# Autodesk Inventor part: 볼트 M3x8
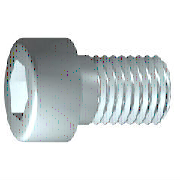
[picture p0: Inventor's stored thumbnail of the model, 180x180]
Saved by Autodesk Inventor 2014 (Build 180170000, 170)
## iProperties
IsCustomPart: 0
Created: 2012-02
Part Number: 볼트 M3x8
Material: 강철, 연강
Description: 6각머리 태핑 나사
Document SubType Name: Modeling
Standard: KS B 1003
Designer: mduedu
Standards Organization: KS
Language: ko-KR
Size Designation: M 3 x 8
Categories: <MemberInstance><Categories><Category DisplayName="조임쇠" InternalName="e4da775c-781d-43d5-af7c-5136215cf5a6" Mnemonic="FSTN"><Category DisplayName="볼트" InternalN
Density: 1 g/cm^3
Appearance: 강철
Author: mduedu
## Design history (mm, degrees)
sketch "스케치1"
  geometry: L1 (-0.867, 0)-(8, 0); L2 (8, 0)-(8, 1.5); L3 (8, 1.5)-(1.25, 1.5); L4 (1.25, 1.5)-(0.943, 1.5); L5 (0.943, 1.5)-(0, 1.5); L6 (0, 1.5)-(0, 2.75); L7 (0, 2.75)-(-3, 2.75); L8 (-3, 2.75)-(-3, 1.443); L9 (-3, 1.443)-(-1.7, 1.443); L10 (-1.7, 1.443)-(-0.867, 0); L11 (-5.2, 0)-(10.2, 0) reference; L12 (0, -0.55)-(0, 3.3) reference; L13 (1.25, 1.5)-(0, 1.5)
  constraints: 22 end point, 6 parallel, 2 collinear, 2 perpendicular, 1 horizontal, 1 point on line
  dimensions: "d1" = 6.75 distance from line of L3.end L2 (= GEL); "d2" = 0.30683 distance of L4.end L3.end (computed from GAL); "d3" = 3 distance between parallel lines of L8 L6 (= KOH); "d4" = 1.3 distance of L8.end L9.end (= INTI); "d5" = 60 deg angle of L10 L1; "d6" = 3 diameter of L3 L1 (= GD); "d7" = 3 diameter of L5 L1 (= BDM); "d8" = 2.88675 diameter of L9 L1 (= 1.1547 x SW); "d9" = 5.5 diameter of L7 L1 (= KOD); "d26" = 8 distance between parallel lines of L12 L2 (= NLG)
revolve "본체" sketch "스케치1" stored, may be unused: angle "d10" = 90 deg
sketch "스케치2"
  geometry: L1 (0, -3.85)-(0, 3.85) reference; L2 (-3.85, 0)-(3.85, 0) reference; L3 (1.443, 0)-(0.722, -1.25); L4 (0.722, -1.25)-(-0.722, -1.25); L5 (-0.722, -1.25)-(-1.443, 0); L6 (-1.443, 0)-(-0.722, 1.25); L7 (-0.722, 1.25)-(0.722, 1.25); L8 (0.722, 1.25)-(1.443, 0); 2 further points
  constraints: 12 end point, 1 coincident, 1 horizontal alignment, 1 point on line, 12 other
extrude "슬롯" join sketch "스케치2" stored distance "d11" = 10; taper "d12" = 0 deg
workplane "Work Plane1"
fillet "Fillet2" dims "d30" = 0.1 (= R)
body "Solid1"
fillet "모깎기1" dims "d17" = 0.3 (= RR)
feature "스레드" dims "d13" = 6.75 (= GEL), "d14" = 0
chamfer "모따기1" distance "d15" = 0.30673 (= -0.5 x SPD + 0.5 x GD); stored, may be unused: second distance "d16" = 0.30673 (= GUL), angle "d27" = 45 deg
other parameters: "GD" = 3 (= NND) [user parameter; used in 2 equation terms], "NLG" = 8 [user parameter; used in 1 equation term], "GEL" = 6.75 [user parameter; used in 2 equation terms], "KOD" = 5.5 [user parameter; used in 1 equation term], "KOH" = 3 [user parameter; used in 1 equation term], "INTI" = 1.3 [user parameter; used in 1 equation term], "GAL" = 0.30673 (= 0.61345 x PTC) [user parameter; used in 1 equation term], "GUL" = 0.30673 (= 0.61345 x PTC) [user parameter; used in 1 equation term], "BDM" = 3 (= NND) [user parameter; used in 1 equation term], "SW" = 2.5 [user parameter; used in 2 equation terms], "RR" = 0.3 [user parameter; used in 1 equation term], "SPD" = 2.38655 (= NND - 1.2269 x PTC) [user parameter; used in 1 equation term], "d19" = 0, "d28" = 0, "d29" = 0, "R" = 0.1 [user parameter; used in 1 equation term], "PHH" = 0.1 [user parameter], "GD1" = 2.38655 (= THREADDIA - 1.2269 x PTC) [user parameter], "THREADDIA" = 3 [user parameter; used in 1 equation term], "FAWI" = 45 deg [user parameter], "PTC" = 0.5 [user parameter; used in 5 equation terms], "NND" = 3 [user parameter; used in 3 equation terms], "TOA" = 30 deg [user parameter], "E0" = 2.8875 (= 1.155 x SW) [user parameter]
